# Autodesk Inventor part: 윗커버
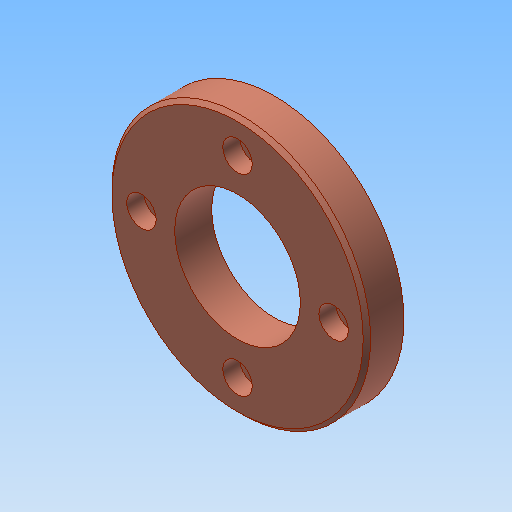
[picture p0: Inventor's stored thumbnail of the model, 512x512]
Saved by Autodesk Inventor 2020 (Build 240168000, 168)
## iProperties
Created: 2023-03
Part Number: 윗커버
Material: 알루미늄 6061
Document SubType Name: Modeling
Designer: mdu-01
Density: 1 g/cm^3
Appearance: 기본값(1)
Author: mdu-01
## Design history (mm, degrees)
sketch "스케치1"
  geometry: C1 r 35 at (0, 0) reference; C2 r 21.5 at (0, 0) reference; C3 r 17 at (0, 0); 1 further point
  constraints: 1 centre point
  dimensions: "d0" = 34 diameter of C3
extrude "돌출1" new body sketch "스케치1" distance "d2" = 10; taper "d3" = 0 deg
chamfer "모따기1" distance "d4" = 1; stored, may be unused: second distance "d5" = 2, angle "d6" = 45 deg
sketch "스케치2" dims "d7" = 52
  geometry: 3 further points
  constraints: 2 vertical alignment, 1 coincident, 2 other
hole "구멍1" sketch "스케치2" at (0, 26) diameter "d9" = 4.5; stored, may be unused: countersink angle "d13" = 90 deg, drill point angle "d15" = 118 deg; dims "d10" = 6, "d11" = 8, "d12" = 4.6, "d14" = 8
node "솔리드1"
pattern_circular "원형 패턴1" dims angle "d17" = 360 deg
node "참조1"
node "참조2"
